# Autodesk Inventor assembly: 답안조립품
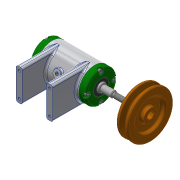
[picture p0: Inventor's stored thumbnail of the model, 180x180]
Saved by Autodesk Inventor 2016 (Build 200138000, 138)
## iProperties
Created: 2020-07
Part Number: 답안조립품
Document SubType Name: Assembly
Designer: user
Author: user
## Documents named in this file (10)
- C:\Users\user\Desktop\700706V1004\답안조립품.iam
- C:\Users\user\Desktop\700706V1004\본체.ipt
- C:\Users\user\Desktop\700706V1004\베어링 6002.ipt
- C:\Users\user\Desktop\700706V1004\축.ipt
- C:\Users\user\Desktop\700706V1004\앞커버.ipt
- C:\Users\user\Desktop\700706V1004\뒤커버.ipt
- C:\Users\user\Desktop\700706V1004\볼트 M4x12.ipt
- C:\Users\user\Desktop\700706V1004\오일 실 15 25 7.ipt
- C:\Users\user\Desktop\700706V1004\키 3x3x12.ipt
- C:\Users\user\Desktop\700706V1004\V벨트풀리.ipt
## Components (1 placed, 1 different names)
1. V벨트풀리:1
